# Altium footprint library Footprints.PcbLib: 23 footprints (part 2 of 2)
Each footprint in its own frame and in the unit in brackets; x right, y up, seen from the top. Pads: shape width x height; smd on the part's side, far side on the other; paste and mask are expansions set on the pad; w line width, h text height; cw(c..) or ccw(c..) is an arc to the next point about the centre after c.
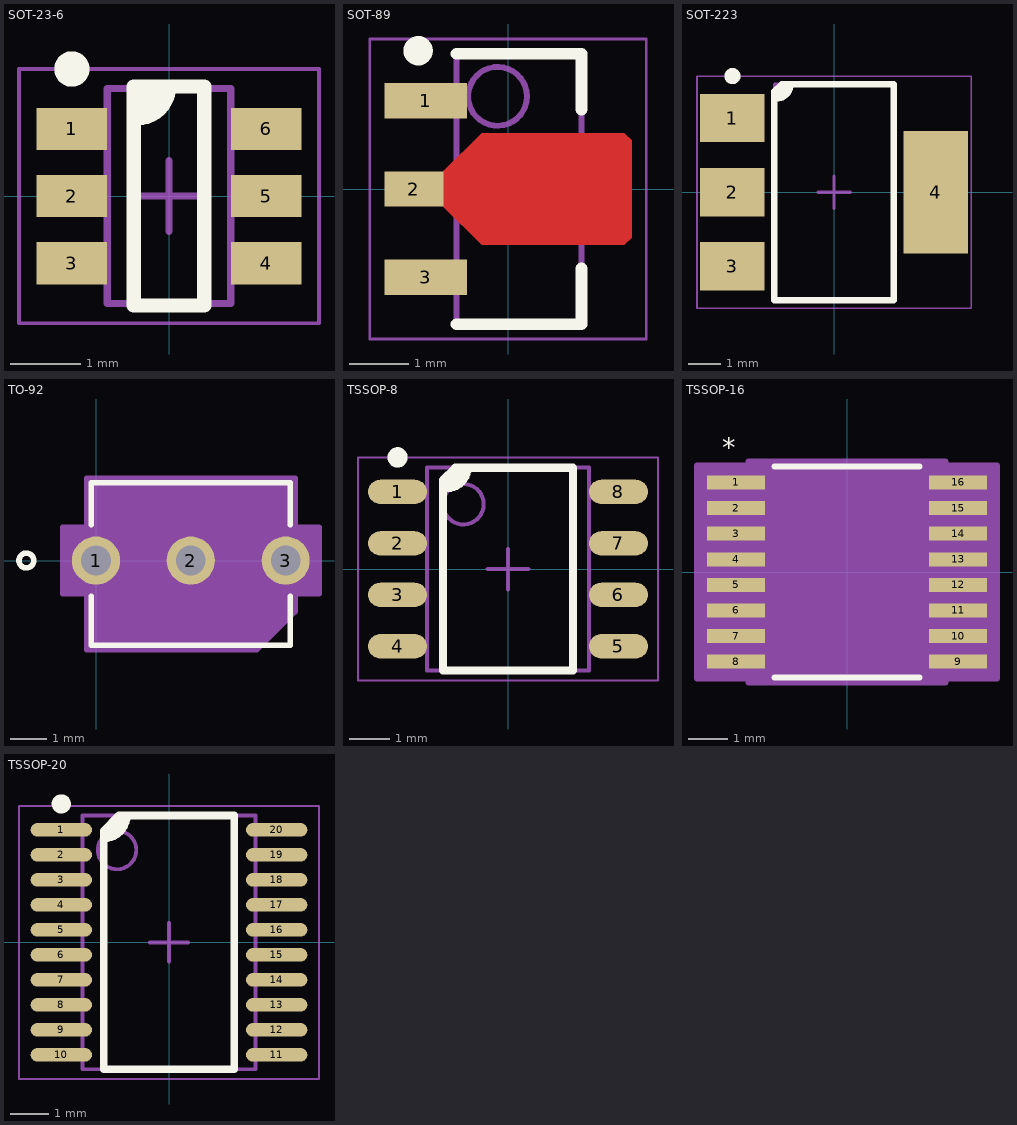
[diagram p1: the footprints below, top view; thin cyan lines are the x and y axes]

## SOT-23-6 [mm] "SOT23, 6-Leads, Body 2.90x2.80mm, Pitch 0.95mm, IPC Medium Density"
height 1.1
pads (6):
  rect 1x0.6 smd: 1(-1.375,0.95) 2(-1.375,0) 3(-1.375,-0.95) 4(1.375,-0.95) 5(1.375,0) 6(1.375,0.95)
Top Overlay:
  circle w0.25: c-1.375,1.8 r0.125
  region: -0.5,1.55 0,1.55 0,1.4 -0.3,1.1 -0.5,1.1
  lines w0.2: -0.5,1.1 -0.45,1.1 ccw(c-0.45,1.55) 0,1.55 ; -0.5,-1.55 0.5,-1.55 0.5,1.55 -0.5,1.55 -0.5,-1.55
Mechanical 13:
  lines w0.1: -0.875,-1.525 -0.875,1.525 0.875,1.525 0.875,-1.525 -0.875,-1.525
Mechanical 15:
  lines w0.05: -2.125,-1.8 -2.125,1.8 2.125,1.8 2.125,-1.8 -2.125,-1.8
  lines w0.1: -0.5,0 0.5,0 ; 0,-0.5 0,0.5
3D body "SOT-23-6.STEP": height 1, standoff 0, extent -1.194,-1.449 1.194,1.451

## SOT-89 [mm] "SOT89, 3-Leads, Body 4.50x2.50mm, Pitch 1.50mm, Lead Span 3.3mm, IPC Medium Density"
height 1.6
pads (3):
  rect 1.4x0.6 smd: 1(-1.4,1.5) 3(-1.4,-1.5)
  rect 1x0.6 smd: 2(-1.6,0)
Top Layer:
  region: -1.1,0.3 -0.45,0.95 1.975,0.95 2.1,0.825 2.1,-0.825 1.975,-0.95 -0.45,-0.95 -1.1,-0.3
Top Overlay:
  circle w0.25: c-1.528,2.35 r0.125
  lines w0.2: -0.878,-2.3 1.25,-2.3 1.25,-1.35 ; -0.878,2.3 1.25,2.3 1.25,1.35
Mechanical 13:
  circle w0.1: c-0.178,1.575 r0.5
  lines w0.1: -0.878,-2.3 1.25,-2.3 1.25,2.3 -0.878,2.3 -0.878,-2.3
Mechanical 15:
  lines w0.05: -2.35,-2.55 2.35,-2.55 2.35,2.55 -2.35,2.55 -2.35,-2.55
  lines w0.1: -0.078,0 0.923,0 ; 0.422,-0.5 0.422,0.5
3D body "SOT-89.STEP": height 1.5, standoff 0, extent -2.05,-2.25 2.1,2.25

## SOT-223 [mm] "SOT223, 4-Leads, Body 6.50x7.00mm (avg), Pitch 2.30mm, IPC Medium Density"
height 1.8
pads (4):
  rect 2x1.5 smd: 1(-3.15,2.3) 2(-3.15,0) 3(-3.15,-2.3)
  rect 2x3.8 smd: 4(3.15,0)
Top Overlay:
  circle w0.25: c-3.15,3.6 r0.125
  region: -1.65,3.275 -1.35,3.35 -1.35,3.2 -1.65,2.9 -1.85,2.9
  lines w0.2: -1.85,2.9 -1.8,2.9 ccw(c-1.8,3.35) -1.35,3.35 ; -1.85,-3.35 1.85,-3.35 1.85,3.35 -1.625,3.35 -1.85,3.125 -1.85,-3.35
Mechanical 13:
  lines w0.1: -1.85,-3.35 -1.85,3.35 1.85,3.35 1.85,-3.35 -1.85,-3.35
Mechanical 15:
  lines w0.05: -4.25,-3.6 -4.25,3.6 4.25,3.6 4.25,-3.6 -4.25,-3.6
  lines w0.1: -0.5,0 0.5,0 ; 0,-0.5 0,0.5
3D body "SOT-223.STEP": height 1.8, standoff 0, extent -3.516,-3.25 3.5,3.25

## TO-92 [mil]
pads (3):
  round 52 / inner round 60 / far side round 52 hole 32 paste-99999 mask+0: 1(0,0) 2(102.36,0) 3(204.72,0)
Top Overlay:
  circle w6: c-75.14,0 r8
  lines w6: -5.14,-38.76 -5.14,-91.24 209.86,-91.24 209.86,-38.76 ; -5.14,38.76 -5.14,83.76 209.86,83.76 209.86,38.76
Mechanical 13:
  circle w0: c14.86,0 r8
  lines w1: -0.14,-86.24 -0.14,78.76 204.86,78.76 204.86,-44.99 163.61,-86.24 -0.14,-86.24
Mechanical 15:
  region: -36,36 -36,-36 -10.04,-36 -10,-96.24 173.61,-96.24 214.86,-54.99 214.86,-36 240.72,-36 240.72,36 214.86,36 214.86,88.76 -10.14,88.76 -10.1,36
  lines w6: -36,-36 -36,36 -10.1,36 -10.14,88.76 214.86,88.76 214.86,36 240.72,36 240.72,-36 214.86,-36 214.86,-54.99 173.61,-96.24 -10,-96.24 -10.04,-36 -36,-36
3D body "2N3904TA.step": height 345.28, standoff -511.81, extent -9.06,-56.3 213.78,86.22

## TSSOP-8 [mm] "SOIC, 8-Leads, Body 4.89x3.90mm, Pitch 1.27mm, IPC Medium Density"
height 1.75
pads (8):
  oval 1.45x0.6 smd: 1(-2.725,1.905) 2(-2.725,0.635) 3(-2.725,-0.635) 4(-2.725,-1.905) 5(2.725,-1.905) 6(2.725,-0.635) 7(2.725,0.635) 8(2.725,1.905)
Top Overlay:
  circle w0.25: c-2.725,2.755 r0.125
  region: -1.3,2.5 -1,2.5 -1,2.401 -1.076,2.217 -1.217,2.076 -1.401,2 -1.5,2 -1.6,2 -1.6,2.2
  lines w0.2: -1.6,2 -1.5,2 ccw(c-1.5,2.5) -1,2.5 ; -1.6,-2.5 1.6,-2.5 1.6,2.5 -1.3,2.5 -1.6,2.2 -1.6,-2.5
Mechanical 13:
  circle w0.1: c-1.1,1.6 r0.5
  lines w0.1: -2,-2.5 -2,2.5 2,2.5 2,-2.5 -2,-2.5
Mechanical 15:
  lines w0.05: -3.7,-2.75 -3.7,2.75 3.7,2.75 3.7,-2.75 -3.7,-2.75
  lines w0.1: -0.5,0 0.5,0 ; 0,-0.5 0,0.5
3D body "SO-8.STEP": height 1.5, standoff 0, extent -3.014,-2.45 3.014,2.45

## TSSOP-16 [mil]
pads (16):
  rect 58x14 smd paste+0 mask+0: 1(-111,89.57) 2(-111,63.98) 3(-111,38.39) 4(-111,12.8) 5(-111,-12.8) 6(-111,-38.39) 7(-111,-63.98) 8(-111,-89.57) 9(111,-89.57) 10(111,-63.98) 11(111,-38.39) 12(111,-12.8) 13(111,12.8) 14(111,38.39) 15(111,63.98) 16(111,89.57)
Top Overlay:
  lines w6: -72.42,-105.5 72.42,-105.5 ; -72.42,105.5 72.42,105.5
  text "*" at -125,115 h19.68
Mechanical 13:
  lines w0: -12,100.5 ccw(c0,100.5) 12,100.5
  lines w1: -126,-95.57 -126,-83.57 -88.5,-83.57 -88.5,-95.57 -126,-95.57 ; -126,-69.98 -126,-57.98 -88.5,-57.98 -88.5,-69.98 -126,-69.98 ; -126,-44.39 -126,-32.39 -88.5,-32.39 -88.5,-44.39 -126,-44.39 ; -126,-18.8 -126,-6.8 -88.5,-6.8 -88.5,-18.8 -126,-18.8 ; -126,6.8 -126,18.8 -88.5,18.8 -88.5,6.8 -126,6.8 ; -126,32.39 -126,44.39 -88.5,44.39 -88.5,32.39 -126,32.39 ; -126,57.98 -126,69.98 -88.5,69.98 -88.5,57.98 -126,57.98 ; -126,83.57 -126,95.57 -88.5,95.57 -88.5,83.57 -126,83.57 ; -88.5,-100.5 88.5,-100.5 88.5,100.5 -88.5,100.5 -88.5,-100.5 ; 88.5,-95.57 88.5,-83.57 126,-83.57 126,-95.57 88.5,-95.57 ; 88.5,-69.98 88.5,-57.98 126,-57.98 126,-69.98 88.5,-69.98 ; 88.5,-44.39 88.5,-32.39 126,-32.39 126,-44.39 88.5,-44.39 ; 88.5,-18.8 88.5,-6.8 126,-6.8 126,-18.8 88.5,-18.8 ; 88.5,6.8 88.5,18.8 126,18.8 126,6.8 88.5,6.8 ; 88.5,32.39 88.5,44.39 126,44.39 126,32.39 88.5,32.39 ; 88.5,57.98 88.5,69.98 126,69.98 126,57.98 88.5,57.98 ; 88.5,83.57 88.5,95.57 126,95.57 126,83.57 88.5,83.57
  text "*" at -86,47.5 h50
Mechanical 15:
  region: -98.5,-106.57 -150,-106.57 -150,106.57 -98.5,106.57 -98.5,110.5 98.5,110.5 98.5,106.57 150,106.57 150,-106.57 98.5,-106.57 98.5,-110.5 -98.5,-110.5
  lines w6: -150,-106.57 -150,106.57 -98.5,106.57 -98.5,110.5 98.5,110.5 98.5,106.57 150,106.57 150,-106.57 98.5,-106.57 98.5,-110.5 -98.5,-110.5 -98.5,-106.57 -150,-106.57
3D body "RU_16_ADI.step": height 47.09, standoff 0, extent -125.98,-100.51 125.98,100.51

## TSSOP-20 [mm] "TSSOP, 20-Leads, Body 6.50x4.40mm, Pitch 0.65mm, IPC Medium Density"
height 1.2
pads (20):
  oval 1.6x0.35 smd: 1(-2.8,2.925) 2(-2.8,2.275) 3(-2.8,1.625) 4(-2.8,0.975) 5(-2.8,0.325) 6(-2.8,-0.325) 7(-2.8,-0.975) 8(-2.8,-1.625) 9(-2.8,-2.275) 10(-2.8,-2.925) 11(2.8,-2.925) 12(2.8,-2.275) 13(2.8,-1.625) 14(2.8,-0.975) 15(2.8,-0.325) 16(2.8,0.325) 17(2.8,0.975) 18(2.8,1.625) 19(2.8,2.275) 20(2.8,2.925)
Top Overlay:
  circle w0.25: c-2.8,3.6 r0.125
  region: -1.7,2.7 -1.581,2.7 -1.36,2.791 -1.191,2.96 -1.1,3.181 -1.1,3.3 -1.4,3.3 -1.7,3
  lines w0.2: -1.7,2.7 ccw(c-1.7,3.3) -1.1,3.3 ; -1.7,-3.3 -1.7,2.9 -1.3,3.3 1.7,3.3 1.7,-3.3 -1.7,-3.3
Mechanical 13:
  circle w0.1: c-1.35,2.4 r0.5
  lines w0.1: -2.25,-3.3 -2.25,3.3 2.25,3.3 2.25,-3.3 -2.25,-3.3
Mechanical 15:
  lines w0.05: -3.9,-3.55 -3.9,3.55 3.9,3.55 3.9,-3.55 -3.9,-3.55
  lines w0.1: -0.5,0 0.5,0 ; 0,-0.5 0,0.5
3D body "TSSOP-20-TI-PW.STEP": height 1.2, standoff 0, extent -3.21,-3.25 3.211,3.25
